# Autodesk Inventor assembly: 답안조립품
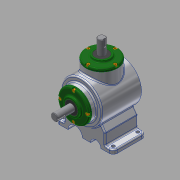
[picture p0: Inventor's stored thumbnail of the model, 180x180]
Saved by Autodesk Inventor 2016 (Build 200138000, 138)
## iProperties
Created: 2018-08
Part Number: 답안조립품
Document SubType Name: Assembly
Designer: Administrator
Author: Administrator
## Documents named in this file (14)
- C:\Users\Administrator\Desktop\480807V1012\답안조립품.iam
- C:\Users\Administrator\Desktop\480807V1012\본체.ipt
- C:\Users\Administrator\Desktop\480807V1012\메인 축.ipt
- 메인 축.ipt
- C:\Users\Administrator\Desktop\480807V1012\베어링 6203.ipt
- C:\Users\Administrator\Desktop\480807V1012\커버.ipt
- C:\Users\Administrator\Desktop\480807V1012\오일실 17 32 8.ipt
- C:\Users\Administrator\Desktop\480807V1012\키 5x5.ipt
- C:\Users\Administrator\Desktop\480807V1012\메인 베벨기어.ipt
- C:\Users\Administrator\Desktop\480807V1012\볼트 M4.ipt
- C:\Users\Administrator\Desktop\480807V1012\서브 축.ipt
- 서브 축.ipt
- C:\Users\Administrator\Desktop\480807V1012\키 4x4.ipt
- C:\Users\Administrator\Desktop\480807V1012\서브 베벨기어.ipt
